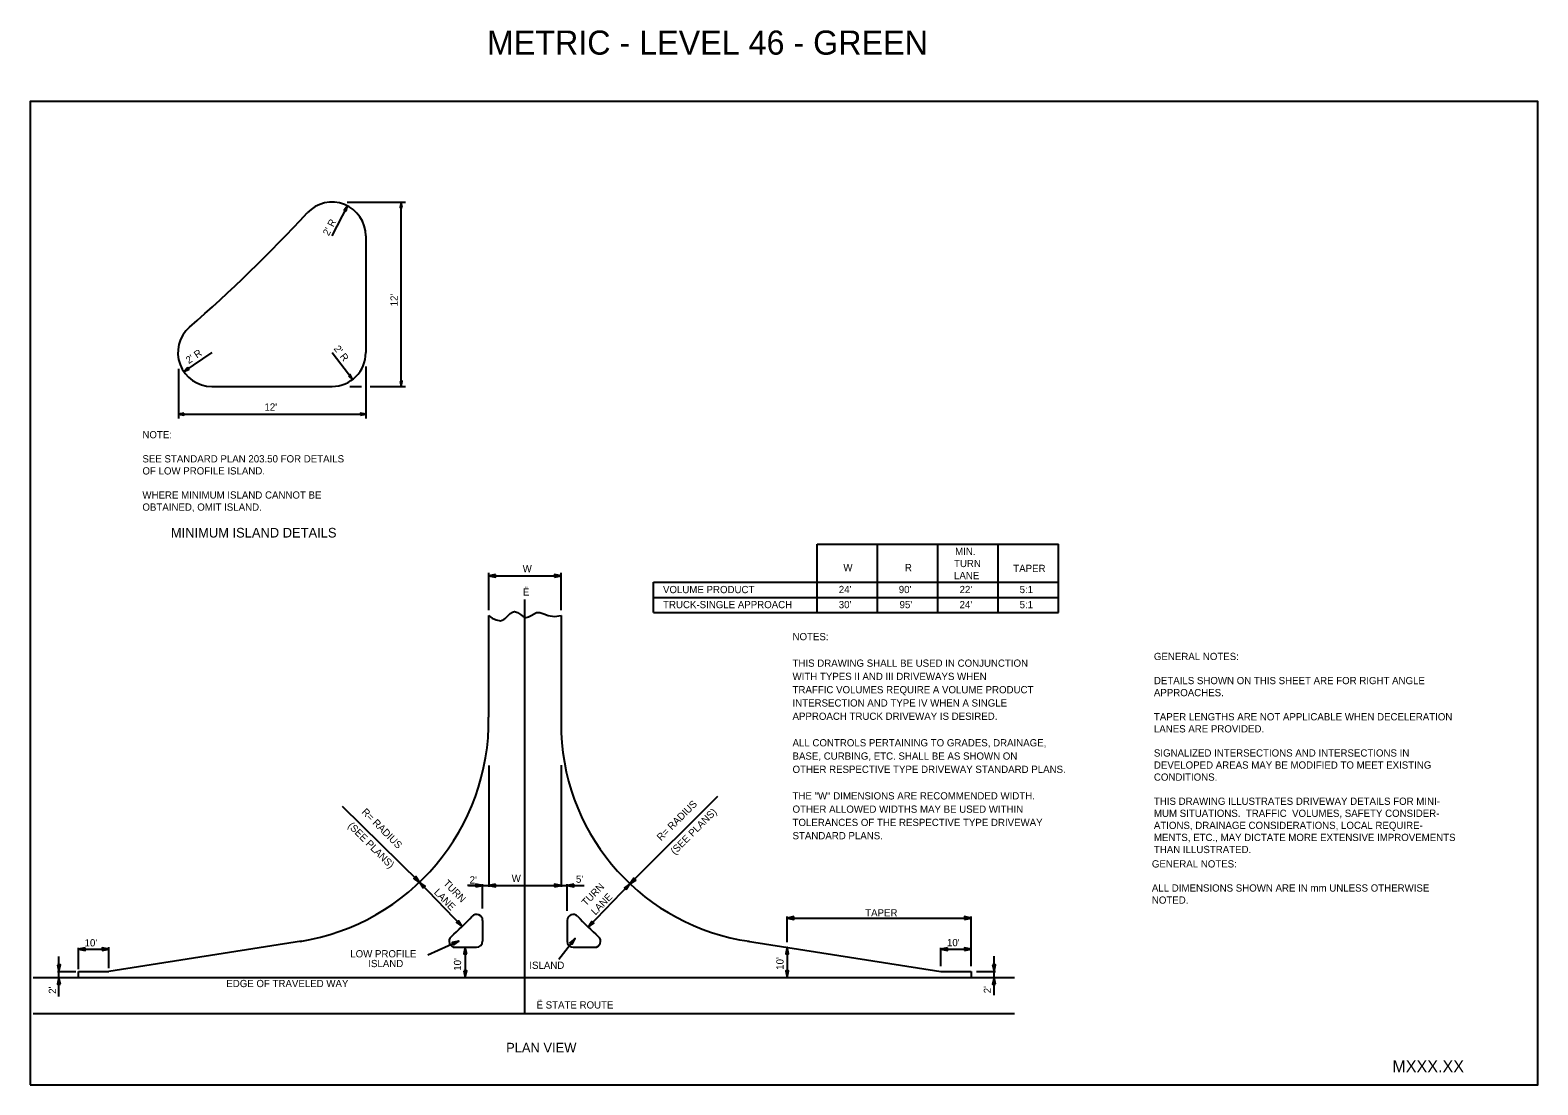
# Model space of a CAD drawing. Extents: x -439.1 to -407.9, y -458.1 to -436.2.
import ezdxf

# ---------------------------------------------------------------- set-up
doc = ezdxf.new("R2010")
doc.units = 0
for name, color, linetype in [('Bridge-Named Boundary', 7, 'Continuous'), ('Default', 7, 'Continuous'), ('Level 4', 7, 'Continuous'), ('Level 46', 7, 'Continuous')]:
    doc.layers.add(name, color=color, linetype=linetype)

msp = doc.modelspace()

# ---------------------------------------------------------------- linework, layer by layer
at = {"layer": 'Bridge-Named Boundary'}
msp.add_lwpolyline([(-439.109, -458.051), (-407.859, -458.051), (-407.859, -437.676), (-439.109, -437.676)], close=True, dxfattribs=at)
at = {"layer": 'Default'}
for p, q in [((-432.852, -440.461), (-432.532, -439.845)), ((-432.54, -439.763), (-431.33, -439.763)), ((-431.418, -443.579), (-431.418, -439.763)), ((-435.346, -442.879), (-435.927, -443.271)), ((-432.852, -442.879), (-432.424, -443.435)), ((-436.036, -443.212), (-436.036, -444.242)), ((-432.152, -443.164), (-432.152, -444.242)), ((-432.48, -443.579), (-432.24, -443.579)), ((-432.064, -443.579), (-431.33, -443.579)), ((-436.036, -444.154), (-432.152, -444.154)), ((-422.795, -448.262), (-422.795, -446.849)), ((-422.795, -446.849), (-417.795, -446.849)), ((-421.545, -448.262), (-421.545, -446.849)), ((-420.295, -448.262), (-420.295, -446.849)), ((-419.045, -448.262), (-419.045, -446.849)), ((-417.795, -448.262), (-417.795, -446.849)), ((-429.605, -448.217), (-429.605, -447.443)), ((-428.105, -448.217), (-428.105, -447.443)), ((-429.605, -447.504), (-428.105, -447.504)), ((-426.191, -447.637), (-417.795, -447.637)), ((-426.191, -448.262), (-426.191, -447.637)), ((-428.856, -456.576), (-428.856, -447.994)), ((-426.191, -447.95), (-417.795, -447.95)), ((-426.191, -448.262), (-417.795, -448.262)), ((-429.605, -451.437), (-429.605, -453.948)), ((-428.105, -451.429), (-428.105, -453.948)), ((-426.676, -453.886), (-424.855, -452.069)), ((-431.041, -453.853), (-432.636, -452.285)), ((-431.138, -453.757), (-431.041, -453.853)), ((-431.041, -453.853), (-431.138, -453.757)), ((-431.041, -453.853), (-430.152, -454.769)), ((-431.04, -453.853), (-430.944, -453.952)), ((-430.944, -453.952), (-431.04, -453.853)), ((-429.73, -453.919), (-430.043, -453.919)), ((-430.025, -453.919), (-427.668, -453.919)), ((-429.73, -454.397), (-429.73, -453.89)), ((-427.98, -454.443), (-427.98, -453.89)), ((-427.98, -453.919), (-427.628, -453.919)), ((-427.545, -454.782), (-426.676, -453.887)), ((-426.578, -453.789), (-426.676, -453.886)), ((-426.676, -453.886), (-426.578, -453.789)), ((-430.248, -454.67), (-430.152, -454.769)), ((-430.152, -454.769), (-430.248, -454.67)), ((-427.545, -454.782), (-427.448, -454.683)), ((-427.448, -454.683), (-427.545, -454.782)), ((-423.418, -455.092), (-423.418, -454.565)), ((-423.418, -454.594), (-419.605, -454.594)), ((-419.605, -455.592), (-419.605, -454.565)), ((-427.545, -454.782), (-427.545, -454.782)), ((-427.545, -454.782), (-427.545, -454.782)), ((-438.105, -455.655), (-438.105, -455.209)), ((-438.105, -455.238), (-437.48, -455.238)), ((-437.48, -455.633), (-437.48, -455.196)), ((-430.221, -455.073), (-430.867, -455.367)), ((-430.221, -455.073), (-430.347, -455.131)), ((-430.347, -455.131), (-430.221, -455.073)), ((-430.09, -455.201), (-430.09, -455.826)), ((-427.814, -455.018), (-428.15, -455.455)), ((-427.898, -455.128), (-427.814, -455.018)), ((-427.898, -455.128), (-427.814, -455.018)), ((-427.814, -455.018), (-427.898, -455.128)), ((-427.898, -455.128), (-427.814, -455.018)), ((-427.814, -455.018), (-427.898, -455.128)), ((-427.814, -455.018), (-427.898, -455.128)), ((-423.418, -455.201), (-423.418, -455.826)), ((-423.418, -455.201), (-423.418, -455.339)), ((-423.418, -455.339), (-423.418, -455.201)), ((-420.23, -455.592), (-420.23, -455.209)), ((-420.23, -455.238), (-419.605, -455.238)), ((-438.512, -456.223), (-438.512, -455.389)), ((-419.131, -456.196), (-419.131, -455.388)), ((-438.541, -455.701), (-438.16, -455.701)), ((-423.418, -455.688), (-423.418, -455.826)), ((-423.418, -455.826), (-423.418, -455.688)), ((-423.418, -455.826), (-423.418, -455.826)), ((-423.418, -455.826), (-423.418, -455.826)), ((-419.496, -455.701), (-419.103, -455.701)), ((-439.044, -456.576), (-418.705, -456.576))]:
    msp.add_line(p, q, dxfattribs=at)
for points in [[(-432.559, -439.947), (-432.528, -439.839), (-432.6, -439.926)], [(-431.395, -439.874), (-431.418, -439.763), (-431.441, -439.874)], [(-435.847, -443.19), (-435.926, -443.271), (-435.821, -443.228)], [(-432.51, -443.36), (-432.425, -443.434), (-432.474, -443.332)], [(-431.441, -443.469), (-431.418, -443.579), (-431.395, -443.469)], [(-435.925, -444.131), (-436.036, -444.154), (-435.925, -444.177)], [(-432.262, -444.177), (-432.152, -444.154), (-432.262, -444.131)], [(-429.467, -447.475), (-429.605, -447.504), (-429.467, -447.533)], [(-428.244, -447.533), (-428.105, -447.504), (-428.244, -447.475)], [(-431.158, -453.777), (-431.04, -453.853), (-431.118, -453.736)], [(-430.924, -453.932), (-431.041, -453.853), (-430.965, -453.972)], [(-429.869, -453.948), (-429.73, -453.919), (-429.869, -453.89)], [(-429.467, -453.89), (-429.605, -453.919), (-429.467, -453.948)], [(-428.244, -453.948), (-428.105, -453.919), (-428.244, -453.89)], [(-427.842, -453.89), (-427.98, -453.919), (-427.842, -453.948)], [(-426.752, -454.006), (-426.676, -453.886), (-426.793, -453.966)], [(-426.752, -454.006), (-426.676, -453.886), (-426.793, -453.966)], [(-426.598, -453.768), (-426.676, -453.886), (-426.558, -453.809)], [(-430.269, -454.689), (-430.152, -454.769), (-430.228, -454.65)], [(-427.469, -454.663), (-427.545, -454.782), (-427.428, -454.703)], [(-423.28, -454.565), (-423.418, -454.594), (-423.28, -454.623)], [(-419.744, -454.623), (-419.605, -454.594), (-419.744, -454.565)], [(-437.967, -455.209), (-438.105, -455.238), (-437.967, -455.266)], [(-437.619, -455.266), (-437.48, -455.238), (-437.619, -455.209)], [(-430.335, -455.157), (-430.221, -455.073), (-430.359, -455.104)], [(-430.061, -455.339), (-430.09, -455.201), (-430.118, -455.339)], [(-427.876, -455.145), (-427.814, -455.018), (-427.921, -455.11)], [(-427.876, -455.145), (-427.814, -455.018), (-427.921, -455.11)], [(-427.876, -455.145), (-427.814, -455.018), (-427.921, -455.11)], [(-423.389, -455.339), (-423.418, -455.201), (-423.447, -455.339)], [(-420.092, -455.209), (-420.23, -455.238), (-420.092, -455.266)], [(-419.744, -455.266), (-419.605, -455.238), (-419.744, -455.209)], [(-438.541, -455.563), (-438.512, -455.701), (-438.483, -455.563)], [(-419.16, -455.563), (-419.131, -455.701), (-419.103, -455.563)], [(-438.483, -455.964), (-438.512, -455.826), (-438.541, -455.964)], [(-430.118, -455.688), (-430.09, -455.826), (-430.061, -455.688)], [(-423.447, -455.688), (-423.418, -455.826), (-423.389, -455.688)], [(-419.103, -455.964), (-419.131, -455.826), (-419.16, -455.964)]]:
    msp.add_lwpolyline(points, close=True, dxfattribs=at)
for points in [[(-429.606, -448.325), (-429.533, -448.378), (-429.448, -448.418), (-429.362, -448.433), (-429.288, -448.412), (-429.261, -448.389), (-429.236, -448.36), (-429.157, -448.281), (-429.114, -448.255), (-429.069, -448.245), (-429.009, -448.264), (-428.949, -448.304), (-428.889, -448.345), (-428.829, -448.365), (-428.777, -448.355), (-428.723, -448.326), (-428.611, -448.266), (-428.579, -448.261), (-428.548, -448.261), (-428.459, -448.29), (-428.371, -448.329), (-428.239, -448.345), (-428.106, -448.326)], [(-431.04, -453.852), (-431.118, -453.736), (-431.138, -453.757)], [(-431.138, -453.757), (-431.158, -453.777), (-431.041, -453.853)], [(-430.944, -453.952), (-430.924, -453.932), (-431.04, -453.853)], [(-431.04, -453.853), (-431.04, -453.853)], [(-431.04, -453.853), (-431.04, -453.853)], [(-431.04, -453.853), (-430.965, -453.972)], [(-430.965, -453.972), (-430.944, -453.952)], [(-426.578, -453.789), (-426.598, -453.768), (-426.676, -453.886)], [(-426.676, -453.886), (-426.558, -453.809)], [(-426.558, -453.809), (-426.578, -453.789)], [(-430.248, -454.67), (-430.269, -454.689), (-430.152, -454.769)], [(-430.152, -454.769), (-430.228, -454.65), (-430.248, -454.67)], [(-427.448, -454.683), (-427.469, -454.663), (-427.545, -454.782)], [(-427.545, -454.782), (-427.428, -454.703), (-427.448, -454.683)], [(-430.221, -455.073), (-430.359, -455.104), (-430.347, -455.131)], [(-430.347, -455.131), (-430.335, -455.157)], [(-430.335, -455.157), (-430.221, -455.073)], [(-427.814, -455.018), (-427.921, -455.11)], [(-427.921, -455.11), (-427.898, -455.128)], [(-427.898, -455.128), (-427.876, -455.145)], [(-427.876, -455.145), (-427.814, -455.018)], [(-423.418, -455.201), (-423.447, -455.339)], [(-423.418, -455.339), (-423.389, -455.339), (-423.418, -455.201)], [(-423.447, -455.339), (-423.418, -455.339)], [(-423.418, -455.688), (-423.447, -455.688), (-423.418, -455.826)], [(-423.418, -455.826), (-423.389, -455.688), (-423.418, -455.688)]]:
    msp.add_lwpolyline(points, dxfattribs=at)
for start, end in [(313.6787, 313.6816), (313.6757, 313.6787)]:
    msp.add_arc((-434.244, -450.498), 4.639, start, end, dxfattribs=at)
at = {"layer": 'Level 4'}
for p, q in [((-432.152, -440.461), (-432.152, -442.879)), ((-435.346, -443.579), (-432.852, -443.579)), ((-429.606, -448.325), (-429.606, -450.43)), ((-428.106, -448.326), (-428.106, -450.76)), ((-429.731, -454.644), (-429.731, -455.076)), ((-427.981, -454.644), (-427.981, -455.076)), ((-433.487, -455.075), (-437.481, -455.701)), ((-430.301, -455.201), (-429.856, -455.201)), ((-427.856, -455.201), (-427.41, -455.201)), ((-424.24, -455.072), (-420.231, -455.701)), ((-439.044, -455.826), (-418.705, -455.826)), ((-438.106, -455.826), (-438.106, -455.701)), ((-438.106, -455.701), (-437.481, -455.701)), ((-420.231, -455.701), (-419.606, -455.701)), ((-419.606, -455.701), (-419.606, -455.826))]:
    msp.add_line(p, q, dxfattribs=at)
for centre, radius, start, end in [((-457.702, -417.329), 33.25, 311.1859, 317.0509), ((-432.852, -440.461), 0.7, 0, 137.0509), ((-435.346, -442.879), 0.7, 131.1859, 270), ((-432.852, -442.879), 0.7, 270, 0), ((-434.244, -450.498), 4.639, 279.0559, 0.8394), ((-423.559, -450.577), 4.546, 182.3067, 261.8659), ((-434.293, -450.513), 5.938, 311.1859, 317.0509), ((-429.855, -454.644), 0.125, 0, 137.0509), ((-427.855, -454.644), 0.125, 42.9491, 180), ((-423.418, -450.513), 5.938, 222.9491, 228.8141), ((-430.301, -455.076), 0.125, 131.1859, 270), ((-427.41, -455.076), 0.125, 270, 48.8141), ((-429.855, -455.076), 0.125, 270, 0), ((-427.855, -455.076), 0.125, 180, 270)]:
    msp.add_arc(centre, radius, start, end, dxfattribs=at)

# ---------------------------------------------------------------- texts
at = {"layer": 'Default'}
for s, rotation, p in [("2' R", 62.5, (-432.92, -440.471)), ("12'", 90, (-431.491, -441.92)), ("2' R", 307.6, (-432.825, -442.799)), ("2' R", 34, (-435.822, -443.118)), ('R= RADIUS', 45, (-426.033, -453.006)), ('R= RADIUS', 315, (-432.249, -452.41)), ('(SEE PLANS)', 45, (-425.747, -453.292)), ('(SEE PLANS)', 315, (-432.535, -452.696)), ('LANE', 314.1, (-430.751, -454.074)), ('TURN', 314.1, (-430.557, -453.886)), ('TURN ', 45.9, (-427.587, -454.357)), ('LANE', 45.9, (-427.393, -454.545)), ("10'", 90, (-430.176, -455.687)), ("10'", 90, (-423.493, -455.667)), ("2'", 90, (-438.574, -456.164)), ("2'", 90, (-419.193, -456.154))]:
    msp.add_text(s, height=0.15, rotation=rotation, dxfattribs=at).set_placement(p)
for s, height, p in [("12'", 0.15, (-434.252, -444.081)), ('TURN', 0.15, (-419.96, -447.323)), ('MIN.', 0.15, (-419.937, -447.073)), ('W', 0.15, (-428.9, -447.43)), ('W', 0.15, (-422.253, -447.409)), ('R', 0.15, (-420.978, -447.409)), ('LANE', 0.15, (-419.96, -447.573)), ('TAPER', 0.15, (-418.732, -447.424)), ('Ë', 0.15, (-428.897, -447.914)), ('VOLUME PRODUCT', 0.15, (-425.992, -447.863)), ("24'", 0.15, (-422.349, -447.862)), ("90'", 0.15, (-421.105, -447.862)), ("22'", 0.15, (-419.845, -447.862)), ('5:1', 0.15, (-418.6, -447.862)), ('TRUCK-SINGLE APPROACH', 0.15, (-425.99, -448.175)), ("30'", 0.15, (-422.349, -448.175)), ("95'", 0.15, (-421.089, -448.175)), ("24'", 0.15, (-419.845, -448.175)), ('5:1', 0.15, (-418.6, -448.175)), ('NOTES:', 0.15, (-423.307, -448.838)), ('THIS DRAWING SHALL BE USED IN CONJUNCTION ', 0.15, (-423.307, -449.388)), ('GENERAL NOTES:', 0.15, (-415.817, -449.249)), ('WITH TYPES II AND III DRIVEWAYS WHEN ', 0.15, (-423.307, -449.663)), ('DETAILS SHOWN ON THIS SHEET ARE FOR RIGHT ANGLE ', 0.15, (-415.817, -449.749)), ('TRAFFIC VOLUMES REQUIRE A VOLUME PRODUCT ', 0.15, (-423.307, -449.938)), ('APPROACHES.  ', 0.15, (-415.817, -449.999)), ('INTERSECTION AND TYPE IV WHEN A SINGLE ', 0.15, (-423.307, -450.213)), ('APPROACH TRUCK DRIVEWAY IS DESIRED.  ', 0.15, (-423.307, -450.488)), ('TAPER LENGTHS ARE NOT APPLICABLE WHEN DECELERATION ', 0.15, (-415.817, -450.499)), ('LANES ARE PROVIDED.  ', 0.15, (-415.817, -450.749)), ('ALL CONTROLS PERTAINING TO GRADES, DRAINAGE, ', 0.15, (-423.307, -451.038)), ('BASE, CURBING, ETC. SHALL BE AS SHOWN ON', 0.15, (-423.307, -451.313)), ('SIGNALIZED INTERSECTIONS AND INTERSECTIONS IN ', 0.15, (-415.817, -451.249)), ('OTHER RESPECTIVE TYPE DRIVEWAY STANDARD PLANS.  ', 0.15, (-423.307, -451.588)), ('DEVELOPED AREAS MAY BE MODIFIED TO MEET EXISTING ', 0.15, (-415.817, -451.499)), ('CONDITIONS.  ', 0.15, (-415.817, -451.749)), ('THE "W" DIMENSIONS ARE RECOMMENDED WIDTH.  ', 0.15, (-423.307, -452.138)), ('THIS DRAWING ILLUSTRATES DRIVEWAY DETAILS FOR MINI-', 0.15, (-415.817, -452.249)), ('OTHER ALLOWED WIDTHS MAY BE USED WITHIN ', 0.15, (-423.307, -452.413)), ('MUM SITUATIONS.  TRAFFIC  VOLUMES, SAFETY CONSIDER-', 0.15, (-415.817, -452.499)), ('TOLERANCES OF THE RESPECTIVE TYPE DRIVEWAY ', 0.15, (-423.307, -452.688)), ('STANDARD PLANS.', 0.15, (-423.307, -452.963)), ('ATIONS, DRAINAGE CONSIDERATIONS, LOCAL REQUIRE-', 0.15, (-415.817, -452.749)), ('THAN ILLUSTRATED.', 0.15, (-415.817, -453.249)), ('MENTS, ETC., MAY DICTATE MORE EXTENSIVE IMPROVEMENTS ', 0.15, (-415.817, -452.999)), ("2'", 0.15, (-430, -453.879)), ('W', 0.15, (-429.128, -453.848)), ("5'", 0.15, (-427.796, -453.864)), ('TAPER', 0.15, (-421.801, -454.561)), ("10'", 0.15, (-437.981, -455.183)), ('LOW PROFILE', 0.15, (-432.474, -455.41)), ("10'", 0.15, (-420.106, -455.178)), ('ISLAND', 0.15, (-432.1, -455.612)), (' ISLAND', 0.15, (-428.818, -455.648)), ('EDGE OF TRAVELED WAY', 0.15, (-435.043, -456.026)), ('Ë STATE ROUTE', 0.15, (-428.613, -456.47)), ('PLAN VIEW', 0.2, (-429.243, -457.38))]:
    msp.add_text(s, height=height, dxfattribs=at).set_placement(p)
at = {"layer": 'Level 4'}
for s, height, p in [('NOTE:', 0.15, (-436.782, -444.654)), ('SEE STANDARD PLAN 203.50 FOR DETAILS ', 0.15, (-436.782, -445.154)), ('OF LOW PROFILE ISLAND.  ', 0.15, (-436.782, -445.404)), ('WHERE MINIMUM ISLAND CANNOT BE ', 0.15, (-436.782, -445.904)), ('OBTAINED, OMIT ISLAND.', 0.15, (-436.782, -446.154)), ('MINIMUM ISLAND DETAILS', 0.2, (-436.192, -446.71))]:
    msp.add_text(s, height=height, dxfattribs=at).set_placement(p)
at = {"layer": 'Level 46'}
for s, height, p in [('METRIC - LEVEL 46 - GREEN', 0.5, (-429.642, -436.705)), ('GENERAL NOTES:', 0.15, (-415.859, -453.547)), ('ALL DIMENSIONS SHOWN ARE IN mm UNLESS OTHERWISE ', 0.15, (-415.859, -454.047)), ('NOTED.', 0.15, (-415.859, -454.297)), ('MXXX.XX', 0.25, (-410.875, -457.792))]:
    msp.add_text(s, height=height, dxfattribs=at).set_placement(p)

doc.saveas('drawing.dxf')
